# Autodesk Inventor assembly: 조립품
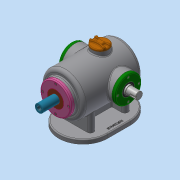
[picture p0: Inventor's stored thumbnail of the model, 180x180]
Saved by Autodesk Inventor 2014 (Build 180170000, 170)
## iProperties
Created: 2022-08
Part Number: 조립품
Document SubType Name: Assembly
Designer: dg
Mass: 8316.85 g
Surface Area: 4266.62 cm^2
Volume: 2093.19 cm^3
Density: 3.97329 g/cm^3
Author: dg
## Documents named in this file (16)
- C:\Users\dg\Desktop\620806V1008\조립품.iam
- C:\Users\dg\Desktop\620806V1008\본체.ipt
- C:\Users\dg\Desktop\620806V1008\가변스프링.ipt
- C:\Users\dg\Desktop\620806V1008\베어링 6205.ipt
- 베어링 6205.ipt
- C:\Users\dg\Desktop\620806V1008\볼트 M4x0.7.ipt
- C:\Users\dg\Desktop\620806V1008\부시.ipt
- C:\Users\dg\Desktop\620806V1008\상부 캡.ipt
- C:\Users\dg\Desktop\620806V1008\슬라이드 커버.ipt
- C:\Users\dg\Desktop\620806V1008\슬라이드.ipt
- C:\Users\dg\Desktop\620806V1008\오일실.ipt
- 오일실.ipt
- C:\Users\dg\Desktop\620806V1008\축 커버-1.ipt
- C:\Users\dg\Desktop\620806V1008\축 커버-2.ipt
- C:\Users\dg\Desktop\620806V1008\편심축.ipt
- C:\Users\dg\Desktop\620806V1008\플레이트.ipt
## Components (14 placed, 3 different names)
1. 가변스프링:1
2. M4x0.7:1
3. 플레이트:1
4. M4x0.7:2
5. M4x0.7:3
6. M4x0.7:4
7. M4x0.7:5
8. M4x0.7:6
9. M4x0.7:7
10. M4x0.7:8
11. M4x0.7:9
12. M4x0.7:10
13. M4x0.7:11
14. M4x0.7:12
